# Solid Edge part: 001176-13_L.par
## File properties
Last saved by: morva
Revision: 82
Accuracy: 0.990
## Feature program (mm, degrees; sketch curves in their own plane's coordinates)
body "unnamed Body 1"
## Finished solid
Body 1: solid body, 26 faces, 53 edges, 31 vertices.
  Faces by surface: cone 9, plane 9, cylinder 4, torus 4
  Edges by curve: circle 23, curve on surface 15, line 13, spline 2
Bounding box of the edges (mm; curved faces can reach further): 15.236 x 30.594 x 11.401, from (485.8869, 411.9379, -99.9139) to (501.1231, 442.5319, -88.5133).
Cylindrical faces by radius (mm): R3 x2, R5 x2
Conical faces (half-angle, radius in mm at the cone's reference point): 45 deg R2.8868 x7, 45 deg R3 x2
Toroidal faces (ring radius, tube radius in mm): R0.3636 r5.2939 x2, R4 r1 x2
Planar faces by outward normal: oblique 9
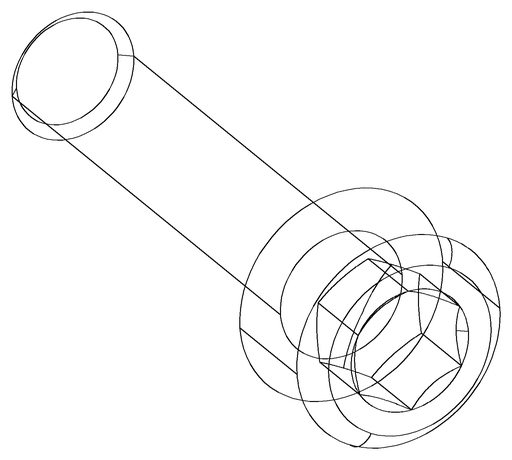
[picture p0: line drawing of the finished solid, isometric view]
